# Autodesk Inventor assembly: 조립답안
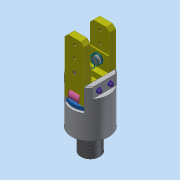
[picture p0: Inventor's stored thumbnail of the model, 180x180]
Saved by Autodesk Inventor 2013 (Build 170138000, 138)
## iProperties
Created: 2019-02
Part Number: 조립답안
Document SubType Name: Assembly
Designer: Administrator
Author: Administrator
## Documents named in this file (11)
- C:\Users\Administrator\Desktop\490207V1003\조립답안.iam
- C:\Users\Administrator\Desktop\490207V1003\본체.ipt
- C:\Users\Administrator\Desktop\490207V1003\O-링.ipt
- C:\Users\Administrator\Desktop\490207V1003\피스톤.ipt
- C:\Users\Administrator\Desktop\490207V1003\핑거.ipt
- C:\Users\Administrator\Desktop\490207V1003\평행핀 6x28.ipt
- C:\Users\Administrator\Desktop\490207V1003\부시.ipt
- C:\Users\Administrator\Desktop\490207V1003\핀.ipt
- C:\Users\Administrator\Desktop\490207V1003\E-링.ipt
- C:\Users\Administrator\Desktop\490207V1003\가이드핀.ipt
- C:\Users\Administrator\Desktop\490207V1003\스프링.ipt
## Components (13 placed, 6 different names)
1. O-링:1
2. 피스톤:1
3. O-링:2
4. 핑거:1 — 플러쉬:1
5. 핑거:2 — 플러쉬:2
6. 핀:1
7. 핀:2
8. E-링:1
9. E-링:2
10. E-링:3
11. E-링:4
12. 가이드핀:1
13. 가이드핀:2
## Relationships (2: Flush 2)
- 플러쉬:1 [Flush]: 핑거:1
- 플러쉬:2 [Flush]: 핑거:2
